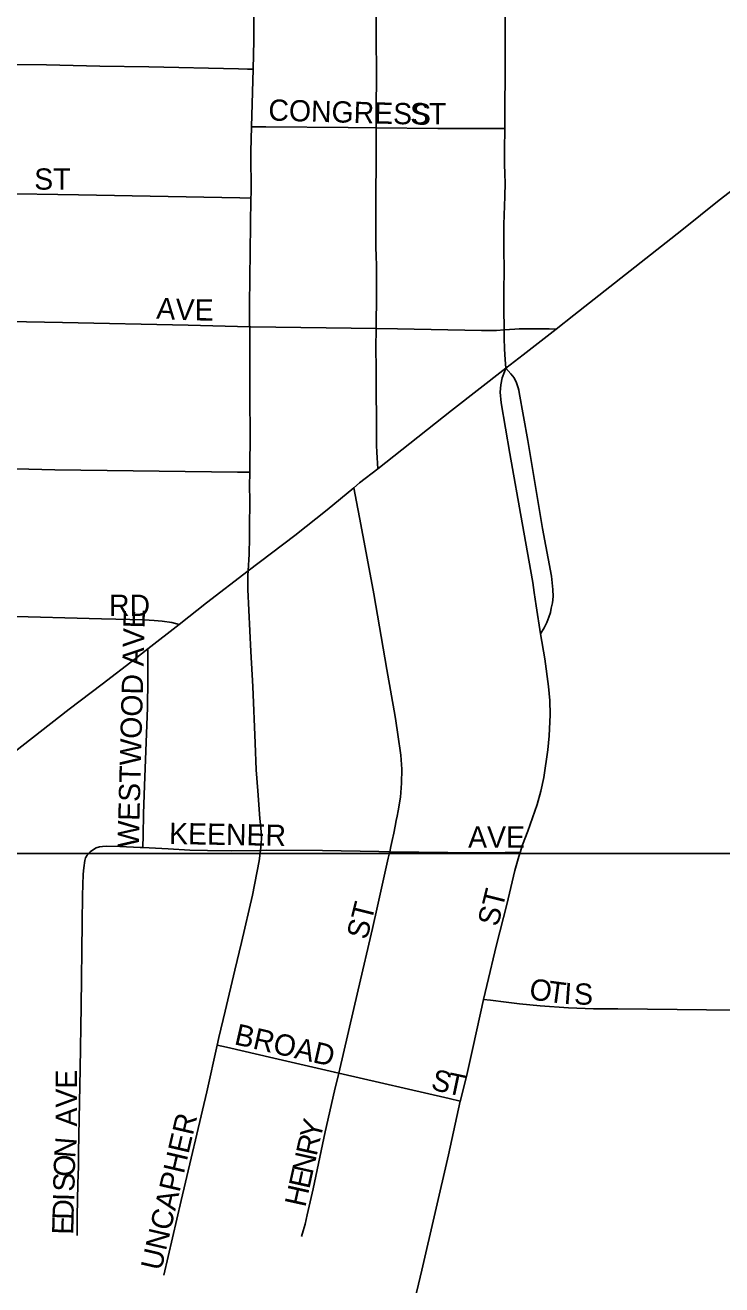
# Model space of a CAD drawing. Extents: x -9.1 to 34, y -3.1 to 22.
# Drawn here: x 4.372 to 4.682, y 18.579 to 19.14 of the extents above; entities that cross this region are included whole.
import ezdxf

# ---------------------------------------------------------------- set-up
doc = ezdxf.new("R2010")
doc.units = 0
for name, color, linetype in [('GM_X_City_Street', 7, 'Continuous'), ('GM_X_City_Street_Text', 7, 'Continuous'), ('GM_X_Section', 7, 'Continuous'), ('GM_X_State_Route', 7, 'Continuous')]:
    doc.layers.add(name, color=color, linetype=linetype)

msp = doc.modelspace()

# ---------------------------------------------------------------- linework, layer by layer
at = {"layer": 'GM_X_City_Street'}
for points in [[(4.52823, 19.09449), (4.52824, 19.10766), (4.52829, 19.11314), (4.52834, 19.11834), (4.52833, 19.12176), (4.5282, 19.13165), (4.52824, 19.13788), (4.52828, 19.15343), (4.52858, 19.17828), (4.5288, 19.20936), (4.52889, 19.22802), (4.52888, 19.234), (4.52919, 19.24957), (4.52919, 19.25545), (4.52919, 19.26195), (4.52928, 19.26721), (4.52934, 19.2707), (4.52936, 19.27364), (4.52936, 19.27399)], [(4.58549, 19.09408), (4.58555, 19.10267), (4.58558, 19.10633), (4.58562, 19.11561), (4.58572, 19.11872), (4.58569, 19.12809), (4.58567, 19.14049), (4.58567, 19.14209), (4.5857, 19.14832), (4.58581, 19.16699), (4.58565, 19.17317), (4.58549, 19.17932), (4.58577, 19.20422), (4.58565, 19.2066), (4.58554, 19.20993), (4.58532, 19.21905), (4.58565, 19.27189), (4.58565, 19.27319)], [(4.47341, 19.12055), (4.47373, 19.13334), (4.47371, 19.14323), (4.47359, 19.15195), (4.47356, 19.17683), (4.47366, 19.18435)], [(4.35657, 19.12264), (4.38127, 19.12251), (4.4051, 19.12192), (4.42691, 19.12157), (4.46688, 19.12069), (4.47084, 19.1206), (4.47341, 19.12055)], [(4.47273, 19.09486), (4.47341, 19.12055)], [(4.47243, 19.06307), (4.47248, 19.06517), (4.47243, 19.08385), (4.47273, 19.09486)], [(4.47273, 19.09486), (4.47901, 19.09482), (4.51581, 19.09461), (4.52823, 19.09449)], [(4.52821, 19.00493), (4.52821, 19.0057), (4.52837, 19.01981), (4.52842, 19.02496), (4.52832, 19.02898), (4.5283, 19.03308), (4.52821, 19.03717), (4.52811, 19.04122), (4.52812, 19.04672), (4.52812, 19.05157), (4.52813, 19.05845), (4.52813, 19.06744), (4.5282, 19.07652), (4.52828, 19.08286), (4.52822, 19.08901), (4.52823, 19.09449)], [(4.52823, 19.09449), (4.55571, 19.09418), (4.57934, 19.0941), (4.58549, 19.09408)], [(4.58522, 19.00433), (4.58514, 19.01401), (4.58506, 19.0202), (4.58519, 19.03264), (4.58505, 19.03889), (4.58514, 19.0513), (4.58552, 19.06376), (4.58563, 19.06999), (4.58556, 19.07373), (4.58547, 19.07846), (4.58546, 19.0847), (4.58549, 19.09408)], [(4.35643, 19.06522), (4.35842, 19.06519), (4.39555, 19.06464), (4.4675, 19.06317), (4.47243, 19.06307)], [(4.47186, 19.00573), (4.47183, 19.00618), (4.47179, 19.0108), (4.47184, 19.01547), (4.47243, 19.06307)], [(4.35627, 19.00821), (4.38849, 19.00769), (4.44449, 19.00653), (4.47186, 19.00573)], [(4.47189, 18.94088), (4.47209, 18.95953), (4.47194, 18.97198), (4.47186, 19.00573)], [(4.47186, 19.00573), (4.47242, 19.00571), (4.52821, 19.00493)], [(4.5289, 18.94247), (4.52847, 18.94981), (4.5283, 18.9529), (4.5283, 18.96535), (4.52826, 18.97613), (4.52823, 18.98709), (4.52813, 18.99638), (4.52821, 19.00493)], [(4.52821, 19.00493), (4.53778, 19.00477), (4.57518, 19.00403), (4.57673, 19.00404), (4.5791, 19.00404), (4.58088, 19.00406), (4.58186, 19.00412), (4.58522, 19.00433)], [(4.58606, 18.98729), (4.58562, 18.99119), (4.58542, 18.99578), (4.58519, 19.00081), (4.58522, 19.00433)], [(4.58522, 19.00433), (4.59002, 19.00471), (4.59187, 19.00478), (4.5943, 19.00488), (4.59743, 19.00482), (4.60524, 19.00477), (4.60835, 19.00474)], [(4.60151, 18.86894), (4.59957, 18.88131), (4.59866, 18.88735), (4.59804, 18.8918), (4.59322, 18.9183), (4.58777, 18.94921), (4.58384, 18.97187), (4.58344, 18.9766), (4.58375, 18.9799), (4.58442, 18.98295), (4.58545, 18.98568), (4.58606, 18.98729)], [(4.60151, 18.86894), (4.60309, 18.87151), (4.60431, 18.8739), (4.60512, 18.87628), (4.60582, 18.87839), (4.60626, 18.88032), (4.60675, 18.88274), (4.60715, 18.88547), (4.60696, 18.88857), (4.60628, 18.89456), (4.6024, 18.91578), (4.59574, 18.95505), (4.59187, 18.97651), (4.59171, 18.97743), (4.59144, 18.97855), (4.59122, 18.97947), (4.59077, 18.98078), (4.5897, 18.98302), (4.58828, 18.98475), (4.58606, 18.98729)], [(4.35606, 18.94276), (4.38497, 18.94205), (4.4665, 18.94095), (4.47189, 18.94088)], [(4.47121, 18.89689), (4.47168, 18.90433), (4.47162, 18.90651), (4.4717, 18.90973), (4.4717, 18.91591), (4.47185, 18.9285), (4.47182, 18.93467), (4.47189, 18.94088)], [(4.53431, 18.77178), (4.53478, 18.77404), (4.53537, 18.77675), (4.53609, 18.78004), (4.53666, 18.78318), (4.53714, 18.78574), (4.53756, 18.78764), (4.53798, 18.78997), (4.53902, 18.79611), (4.53957, 18.80234), (4.53963, 18.80858), (4.5392, 18.81478), (4.53794, 18.82396), (4.53695, 18.83013), (4.53663, 18.83207), (4.53292, 18.85304), (4.52721, 18.88675), (4.52376, 18.90506), (4.52079, 18.92077), (4.51948, 18.92766), (4.51828, 18.93403)], [(4.47664, 18.77232), (4.47686, 18.77398), (4.47705, 18.77751), (4.47696, 18.78032), (4.47688, 18.78249), (4.47642, 18.78653), (4.47556, 18.79887), (4.47477, 18.80823), (4.47425, 18.82013), (4.47323, 18.84544), (4.4724, 18.86098), (4.47101, 18.88863), (4.4711, 18.89508), (4.47121, 18.89689)], [(4.35598, 18.87682), (4.36225, 18.87669), (4.40581, 18.8755), (4.42479, 18.87506), (4.42923, 18.87482), (4.43287, 18.87454), (4.43717, 18.87388), (4.44042, 18.8731)], [(4.59234, 18.77144), (4.59345, 18.77478), (4.59573, 18.78098), (4.59988, 18.79274), (4.60157, 18.79877), (4.60286, 18.80489), (4.60472, 18.81724), (4.60524, 18.82347), (4.60574, 18.83284), (4.60557, 18.83912), (4.60501, 18.84535), (4.6034, 18.8577), (4.60151, 18.86894)], [(4.42428, 18.77361), (4.42435, 18.77919), (4.42448, 18.78864), (4.42493, 18.80125), (4.4263, 18.83591), (4.42645, 18.84847), (4.42648, 18.85475), (4.42651, 18.86223)], [(4.39492, 18.60062), (4.39504, 18.60926), (4.39534, 18.62376), (4.39554, 18.63154), (4.39551, 18.63773), (4.3963, 18.67493), (4.39681, 18.70284), (4.39725, 18.74007), (4.39743, 18.75229), (4.39765, 18.76179), (4.39789, 18.76456), (4.3984, 18.7679), (4.39873, 18.76903), (4.39943, 18.77026), (4.40073, 18.77173)], [(4.40073, 18.77173), (4.4022, 18.77273), (4.40351, 18.77343), (4.4049, 18.77389), (4.40629, 18.77412), (4.40798, 18.7742), (4.41393, 18.77409), (4.4231, 18.77366), (4.42428, 18.77361)], [(4.42428, 18.77361), (4.43559, 18.77305), (4.44523, 18.77243), (4.45302, 18.77228), (4.46387, 18.77208), (4.47664, 18.77232)], [(4.45734, 18.68553), (4.45807, 18.68888), (4.46095, 18.70073), (4.4653, 18.71903), (4.46828, 18.73122), (4.4731, 18.75243), (4.47604, 18.76772), (4.47664, 18.77232)], [(4.47664, 18.77232), (4.47945, 18.77238), (4.50435, 18.77226), (4.52935, 18.77185), (4.53431, 18.77178)], [(4.51155, 18.67298), (4.5202, 18.71026), (4.52661, 18.73752), (4.52888, 18.74756), (4.53353, 18.76887), (4.53419, 18.77128), (4.53431, 18.77178)], [(4.53431, 18.77178), (4.57314, 18.77121), (4.58569, 18.77136), (4.59234, 18.77144)], [(4.57609, 18.70589), (4.57749, 18.71213), (4.58187, 18.73021), (4.58651, 18.74828), (4.58998, 18.76338), (4.59175, 18.76968), (4.59234, 18.77144)], [(4.56565, 18.66061), (4.56572, 18.66091), (4.5687, 18.67287), (4.57142, 18.68496), (4.57609, 18.70589)], [(4.57609, 18.70589), (4.5791, 18.70553), (4.58614, 18.70468), (4.59201, 18.70398), (4.60136, 18.70304), (4.61387, 18.70216), (4.62504, 18.70178), (4.63584, 18.70173), (4.70177, 18.70105), (4.70805, 18.70115), (4.71316, 18.70123)], [(4.43363, 18.58298), (4.44138, 18.61628), (4.45274, 18.66471), (4.45734, 18.68553)], [(4.45734, 18.68553), (4.46155, 18.68457), (4.48257, 18.67975), (4.50958, 18.67342), (4.51155, 18.67298)], [(4.49488, 18.60019), (4.49573, 18.60281), (4.49654, 18.60574), (4.49752, 18.60994), (4.50016, 18.62143), (4.50545, 18.64696), (4.5097, 18.6651), (4.51155, 18.67298)], [(4.51155, 18.67298), (4.56067, 18.66175), (4.56565, 18.66061)], [(4.47636, 18.27506), (4.48661, 18.31901), (4.49442, 18.35546), (4.50193, 18.38876), (4.51566, 18.44616), (4.52552, 18.48852), (4.53842, 18.54291), (4.54863, 18.58519), (4.56037, 18.63668), (4.56565, 18.66061)]]:
    msp.add_lwpolyline(points, dxfattribs=at)
at = {"layer": 'GM_X_Section'}
for points in [[(4.2285, 19.77719), (5.226, 19.77229), (5.22068, 18.771), (4.22542, 18.77097)], [(4.22542, 18.77097), (5.22068, 18.771), (5.21493, 17.76405), (4.21254, 17.77165)]]:
    msp.add_lwpolyline(points, close=True, dxfattribs=at)
at = {"layer": 'GM_X_State_Route'}
for points in [[(4.61624, 19.01095), (4.66437, 19.04881), (4.68111, 19.06222), (4.71666, 19.08949), (4.72979, 19.09956), (4.73975, 19.10696), (4.75198, 19.11642), (4.76383, 19.12561)], [(4.58606, 18.98729), (4.59372, 18.99324), (4.60835, 19.00474), (4.61624, 19.01095)], [(4.31477, 18.77541), (4.31995, 18.7794), (4.32609, 18.78401), (4.32911, 18.78636), (4.3323, 18.78877), (4.3567, 18.80803), (4.36689, 18.81608), (4.39139, 18.83527), (4.40119, 18.8428), (4.40613, 18.84638), (4.42078, 18.85774), (4.42651, 18.86223), (4.44042, 18.8731), (4.45267, 18.88268), (4.47121, 18.89689), (4.49199, 18.91277), (4.50642, 18.92413), (4.51828, 18.93403), (4.52079, 18.93612), (4.5289, 18.94247), (4.53609, 18.94811), (4.56183, 18.96848), (4.58606, 18.98729)]]:
    msp.add_lwpolyline(points, dxfattribs=at)

# ---------------------------------------------------------------- texts
at = {"layer": 'GM_X_City_Street_Text'}
for s, height, rotation, p in [('CONGRESS', 0.00947, 358.4089, (4.48009, 19.0977)), ('ST', 0.00947, 0, (4.54335, 19.09604)), ('ST', 0.00947, 0, (4.37585, 19.06687)), ('A', 0.00947, 356.7195, (4.43012, 19.00937)), ('V', 0.00947, 357.831, (4.43864, 19.00888)), ('E', 0.00947, 359.8075, (4.44732, 19.00856)), ('RD', 0.00947, 0, (4.40918, 18.87687)), ('WESTWOOD AVE', 0.0094697, 88.4799, (4.4224, 18.77349)), ('KEENER', 0.00947, 358.9936, (4.43589, 18.7752)), ('AVE', 0.00947, 0, (4.56918, 18.77354)), ('ST', 0.00947, 75.9734, (4.58245, 18.73802)), ('ST', 0.00947, 75.9734, (4.52412, 18.73219)), ('O', 0.00947, 352.349, (4.59609, 18.70602)), ('T', 0.00947, 352.4105, (4.60436, 18.70491)), ('I', 0.00947, 355.8546, (4.61159, 18.70397)), ('S', 0.00947, 359.1163, (4.61633, 18.70364)), ('BROAD', 0.00947, 347.0952, (4.46458, 18.68599)), ('AVE', 0.00947, 90, (4.3949, 18.64926)), ('S', 0.00947, 345.2745, (4.55217, 18.66597)), ('T', 0.00947, 348.0528, (4.55911, 18.66416)), ('UNCAPHER', 0.00947, 76.8917, (4.43244, 18.58466)), ('Y', 0.00947, 76.0486, (4.50326, 18.64301)), ('N', 0.00947, 85.3398, (4.39411, 18.63498)), ('R', 0.00947, 77.5308, (4.50165, 18.63575)), ('O', 0.00947, 88.5138, (4.3939, 18.62679)), ('N', 0.00947, 77.5068, (4.49985, 18.62761)), ('E', 0.00947, 77.5247, (4.49841, 18.6211)), ('S', 0.00947, 88.5248, (4.39373, 18.62013)), ('H', 0.00947, 77.5068, (4.49661, 18.61297)), ('D', 0.00947, 88.5138, (4.3934, 18.60762)), ('I', 0.00947, 88.4696, (4.39362, 18.61595)), ('E', 0.00947, 88.5242, (4.39323, 18.60096))]:
    msp.add_text(s, height=height, rotation=rotation, dxfattribs=at).set_placement(p)

doc.saveas('drawing.dxf')
